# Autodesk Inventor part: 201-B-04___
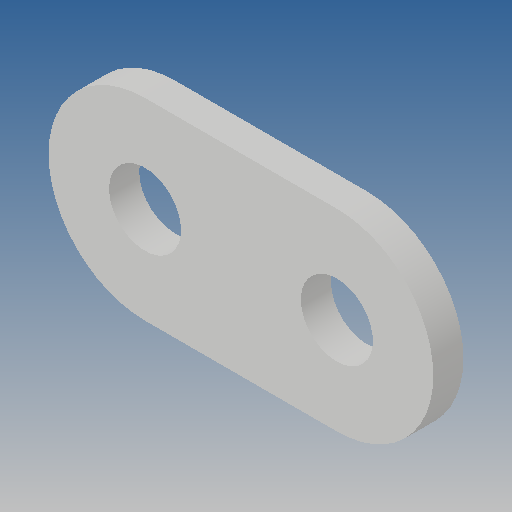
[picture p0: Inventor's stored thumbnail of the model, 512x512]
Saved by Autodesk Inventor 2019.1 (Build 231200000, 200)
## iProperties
Created: 2010-06
Part Number: 201-B-04___
Material: Ogólny
Document SubType Name: Modeling
Designer: CADENGINEERING4
Density: 1 g/cm^3
Appearance: Domyślna
Author: CADENGINEERING4
Revision Number: ANY
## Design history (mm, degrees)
feature "NONE"
node "Bryła1"
